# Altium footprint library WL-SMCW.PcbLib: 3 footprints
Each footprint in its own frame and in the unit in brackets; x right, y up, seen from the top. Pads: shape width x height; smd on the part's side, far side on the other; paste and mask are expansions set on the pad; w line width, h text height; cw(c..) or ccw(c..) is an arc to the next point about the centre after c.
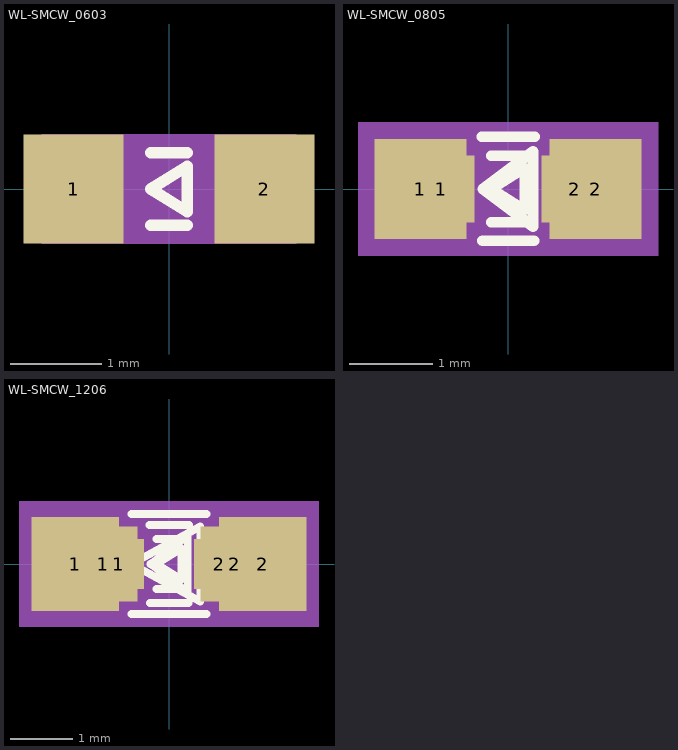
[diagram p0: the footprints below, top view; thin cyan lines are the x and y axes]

## WL-SMCW_0603 [mm]
pads (2):
  rect 1.1x1.2 smd: 1(-1.05,0) 2(1.05,0)
Top Overlay:
  lines w0.127: -0.2,-0.4 0.2,-0.4 ; -0.2,0.4 0.2,0.4 ; -0.2,0 0.2,0.25 0.2,-0.25 -0.2,0
Mechanical 13:
  lines w0.127: -0.8,-0.4 -0.8,0.4 0.8,0.4 0.8,-0.4 -0.8,-0.4
Mechanical 15:
  region: 1.4,-0.6 -1.4,-0.6 -1.4,0.6 1.4,0.6

## WL-SMCW_0805 [mm]
pads (4):
  rect 1.1x1.2 smd: 1(-1.05,0) 2(1.05,0)
  rect 0.8x0.8 smd: 1(-0.8,0) 2(0.8,0)
Top Overlay:
  lines w0.127: -0.313,0.626 0.319,0.626 ; -0.306,-0.623 0.312,-0.623 ; -0.2,-0.4 0.2,-0.4 ; -0.2,0.4 0.2,0.4 ; -0.3,0 0.3,0.45 0.3,-0.45 -0.3,0 ; -0.2,0 0.2,-0.25 0.2,0.25 -0.2,0
Mechanical 13:
  lines w0.127: -1,-0.625 1,-0.625 1,0.625 -1,0.625 -1,-0.625 ; -0.8,-0.4 0.8,-0.4 0.8,0.4 -0.8,0.4 -0.8,-0.4
Mechanical 15:
  region: 1.8,-0.8 -1.8,-0.8 -1.8,0.8 1.8,0.8
  region: 1.4,-0.6 -1.4,-0.6 -1.4,0.6 1.4,0.6

## WL-SMCW_1206 [mm]
pads (6):
  rect 1.4x1.5 smd: 1(-1.5,0) 2(1.5,0)
  rect 1.1x1.2 smd: 1(-1.05,0) 2(1.05,0)
  rect 0.8x0.8 smd: 1(-0.8,0) 2(0.8,0)
Top Overlay:
  lines w0.127: -0.6,-0.8 0.6,-0.8 ; -0.6,0.8 0.6,0.8 ; -0.313,0.626 0.319,0.626 ; -0.306,-0.623 0.312,-0.623 ; -0.2,-0.4 0.2,-0.4 ; -0.2,0.4 0.2,0.4 ; -0.6,0 0.5,0.6 0.5,-0.6 -0.6,0 ; -0.3,0 0.3,0.45 0.3,-0.45 -0.3,0 ; -0.2,0 0.2,-0.25 0.2,0.25 -0.2,0
Mechanical 13:
  lines w0.127: 0.7,0.8 1.6,0.8 1.6,-0.8 -1.6,-0.8 -1.6,0.8 1,0.8 ; -1,-0.625 1,-0.625 1,0.625 -1,0.625 -1,-0.625 ; -0.8,-0.4 0.8,-0.4 0.8,0.4 -0.8,0.4 -0.8,-0.4
Mechanical 15:
  region: 2.4,-1 -2.4,-1 -2.4,1 2.4,1
  region: 1.8,-0.8 -1.8,-0.8 -1.8,0.8 1.8,0.8
  region: 1.4,-0.6 -1.4,-0.6 -1.4,0.6 1.4,0.6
